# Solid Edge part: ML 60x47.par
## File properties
Title: ML 60x47
Author: DESYS
Template: Iso Part.par
Last saved by: Administrator
Revision: 16
Application: Solid Edge
Tipo di contenuto documento: 0
Accuracy: 0,990
Document Number: 3004
Revision: 0
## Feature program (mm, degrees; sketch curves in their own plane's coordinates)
sketch for "unnamed Protrusion 1" plane through (10.8674, 0, 10.8674) normal (0, -1, 0) x-axis (1, 0, 0)
  line (-318.3674, -245.8674) -> (296.6326, -245.8674)
  line (296.6326, -245.8674) -> (296.6326, 224.1326)
  line (296.6326, 224.1326) -> (-318.3674, 224.1326)
  line (-318.3674, 224.1326) -> (-318.3674, -245.8674)
  dimension (linear) = 296.6326
  dimension (linear) = 296.6326
extrude "unnamed Protrusion 1" add finite 50 along -normal
sketch for "ProtrusioneEstrusa_2" plane through (0, 50, 0) normal (0, 1, 0) x-axis (1, 0, 0)
  line (-175, -235) -> (175, -235)
  line (175, -235) -> (175, 115)
  line (175, 115) -> (-175, 115)
  line (-175, 115) -> (-175, -235)
  dimension (linear) = 175
  dimension (linear) = 175
extrude "ProtrusioneEstrusa_2" add finite 90 along +normal
sketch for "ProtrusioneEstrusa_3" plane through (0, 50, 0) normal (0, 1, 0) x-axis (1, 0, 0)
  line (0, 0) -> (0, 0)
  line (-265, -210) -> (265, -210)
  line (265, -210) -> (265, 210)
  line (265, 210) -> (-265, 210)
  line (-265, 210) -> (-265, -210)
  dimension (linear) = 265
  dimension (linear) = 265
extrude "ProtrusioneEstrusa_3" add finite 60 along +normal
sketch for "ScavoEstrusione_3" plane through (0, 0, 0) normal (0, -1, 0) x-axis (0, 0, 1)
  line (-220, -292.5) -> (220, -292.5)
  line (220, -292.5) -> (220, 292.5)
  line (220, 292.5) -> (-220, 292.5)
  line (-220, 292.5) -> (-220, -292.5)
extrude "ScavoEstrusione_3" cut finite 10 along -normal
sketch for "ScavoEstrusione_1" #1 plane through (0, 80, -210) normal (0, 0, -1) x-axis (1, 0, 0)
  arc centre (-148.3706, 107.4441) radius 140 from (-265, 30) to (-175, -30) ccw
  line (-175, -30) -> (-175, -63.2381)
  line (-175, -63.2381) -> (-319.7189, -63.2381)
  line (-319.7189, 30) -> (-319.7189, -63.2381)
  line (-265, 30) -> (-319.7189, 30)
sketch for "ScavoEstrusione_1" #2 plane through (0, 80, -210) normal (0, 0, -1) x-axis (1, 0, 0)
  arc centre (148.3706, 107.4441) radius 140 from (175, -30) to (265, 30) ccw
  line (265, 30) -> (317.0048, 30)
  line (317.0048, 30) -> (317.0048, -58.3528)
  line (317.0048, -58.3528) -> (175, -58.3528)
  line (175, -30) -> (175, -58.3528)
extrude "ScavoEstrusione_1" cut finite 1320 along -normal
sketch for "unnamed Cutout 1" plane through (307.5, 25, 0) normal (1, 0, 0) x-axis (0, 0, 1)
  line (-264.484, -25) -> (-264.484, -119.2302)
  line (-264.484, -119.2302) -> (-115, -119.2302)
  line (-115, -85) -> (-115, -119.2302)
  arc centre (-111.9995, 24.9591) radius 110 from (-210, -25) to (-115, -85) ccw
  line (-264.484, -25) -> (-210, -25)
extrude "unnamed Cutout 1" cut through along -normal
sketch for "ScavoEstrusione_4" plane through (0, 70, 100) normal (0, 0, 1) x-axis (-1, 0, 0)
  line (-140, -40) -> (140, -40)
  arc centre (118.6395, 158.8561) radius 200 from (140, -40) to (292.5, 60) ccw
  line (292.5, 60) -> (292.5, 99.6017)
  line (-292.5, 99.6017) -> (292.5, 99.6017)
  line (-292.5, 60) -> (-292.5, 99.6017)
  arc centre (-118.6395, 158.8561) radius 200 from (-292.5, 60) to (-140, -40) ccw
  dimension (linear) = 140
extrude "ScavoEstrusione_4" cut finite 200 along -normal  Profile_Plane1_Distance = 135 mm
draft "Spoglia_2"  Angles1 = 50 deg
draft "Spoglia_3"  Angles1 = 5 deg
sketch for "ScavoEstrusione_5" plane through (0, 18.0435, 18.0435) normal (1, 0, 0) x-axis (0, 1, 0)
  line (144.3482, -108.0435) -> (101.9565, -108.0435)
  line (101.9565, -108.0435) -> (101.9565, 95.7306)
  line (101.9565, 95.7306) -> (6.9565, 95.7306)
  line (6.9565, 95.7306) -> (6.9565, 196.9565)
  line (6.9565, 196.9565) -> (148.2952, 196.9565)
extrude "ScavoEstrusione_5" cut finite 300 symmetric
sketch for "unnamed Cutout 2" plane through (0, 70, 235) normal (0, 0, 1) x-axis (-1, 0, 0)
  arc centre (0, -121.4286) radius 121.4286 from (-110, -70) to (110, -70) cw
extrude "unnamed Cutout 2" cut through along -normal
sketch for "unnamed Cutout 3" #1 plane through (0, 70, 235) normal (0, 0, 1) x-axis (-1, 0, 0)
  line (107.5, -10) -> (97.5, -10)
  arc centre (97.5, 0) radius 10 from (97.5, 10) to (97.5, -10) ccw
  line (97.5, 10) -> (107.5, 10)
  arc centre (107.5, 0) radius 10 from (107.5, -10) to (107.5, 10) ccw
sketch for "unnamed Cutout 3" #2 plane through (0, 70, 235) normal (0, 0, 1) x-axis (-1, 0, 0)
  line (-107.5, -10) -> (-97.5, -10)
  line (-97.5, 10) -> (-107.5, 10)
  dimension (linear) = 97.5
extrude "unnamed Cutout 3" cut through along -normal
fillet "Rotondo_1" radius 30
sketch for "Foro_1" plane through (0, 10, 120) normal (0, -1, 0) x-axis (0, 0, 1)
  hole centre (50, 0) bore radius 17.5
hole "Foro_1" diameter 35 through
sketch for "ProtrusioneEstrusa_4" plane through (0, 120, -18.4901) normal (0, 1, 0) x-axis (0, 0, 1)
  circle centre (18.4901, 0) radius 35
extrude "ProtrusioneEstrusa_4" add finite 45 along +normal
sketch for "Foro_2" plane through (0, 165, 0) normal (0, 1, 0) x-axis (-1, 0, 0)
  hole centre (0, 0) bore radius 25
hole "Foro_2" diameter 50 through
sketch for "ProtrusioneEstrusa_5" plane through (0, 18.407, 18.407) normal (1, 0, 0) x-axis (0, 1, 0)
  line (6.593, 127.3622) -> (82.392, 118.7377)
  arc centre (75.6089, 59.1223) radius 60 from (82.392, 118.7377) to (135.6089, 59.1223) cw
  line (135.6089, 59.1223) -> (135.6089, 8.8564)
  line (135.6089, 8.8564) -> (95.0929, 8.8564)
  line (95.0929, 8.8564) -> (95.0929, 77.0212)
  line (95.0929, 77.0212) -> (-4.3073, 87.7072)
  line (-4.3073, 87.7072) -> (-4.3073, 127.7833)
  line (-4.3073, 127.7833) -> (6.593, 127.3622)
extrude "ProtrusioneEstrusa_5" add finite 30 symmetric
sketch for "Foro_3" plane through (25.0453, 25.0453, 0) normal (0, 0, -1) x-axis (-1, 0, 0)
  hole centre (25.0453, -0.0453) bore radius 10
hole "Foro_3" diameter 20 to key point
fillet "Rotondo_2" radius 5
fillet "Rotondo_3" radius 10
fillet "Rotondo_4" radius 10
fillet "Rotondo_5" radius 5
fillet "Rotondo_6" radius 10
fillet "Rotondo_7" radius 5
fillet "Rotondo_9" radius 30
fillet "Rotondo_12" radius 10
fillet "Rotondo_13" radius 10
fillet "Rotondo_14" radius 10
fillet "Rotondo_15" radius 10
fillet "Rotondo_16" radius 5
fillet "Rotondo_17" radius 10
fillet "Rotondo_18" radius 5
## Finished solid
Body 1: solid body, 145 faces, 350 edges, 206 vertices.
  Faces by surface: cylinder 67, plane 37, torus 20, blend 19, sphere 2
  Edges by curve: line 157, circle 110, intersection 53, ellipse 30
Bounding box of the edges (mm; curved faces can reach further): 615.000 x 165.000 x 470.000, from (-307.5, 0, -235) to (307.5, 165, 235).
Cylindrical faces by radius (mm): R5 x38, R10 x15, R17.5 x1, R25 x1, R30 x4, R35 x1, R60 x1, R110 x1, R121.4286 x1, R140 x2, R200 x2
Toroidal faces (ring radius, tube radius in mm): R5 r5 x8, R22.5 r5 x1, R30 r5 x1, R35 r5 x2, R35 r10 x1, R44.4524 r10 x1, R45 r10 x1, R55 r5 x2, R130 r10 x2, R131.4286 r10 x1
Spherical faces by radius (mm): R5 x2
Planar faces by outward normal: +x 4, +y 8, +z 7, -x 4, -y 6, -z 5, oblique 3
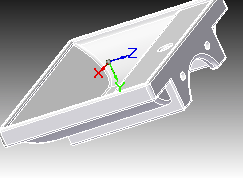
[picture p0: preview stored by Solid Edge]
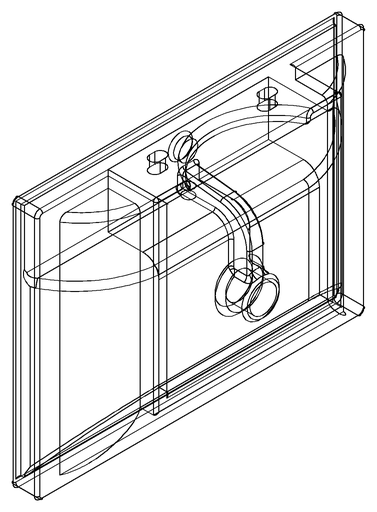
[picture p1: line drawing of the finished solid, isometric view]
